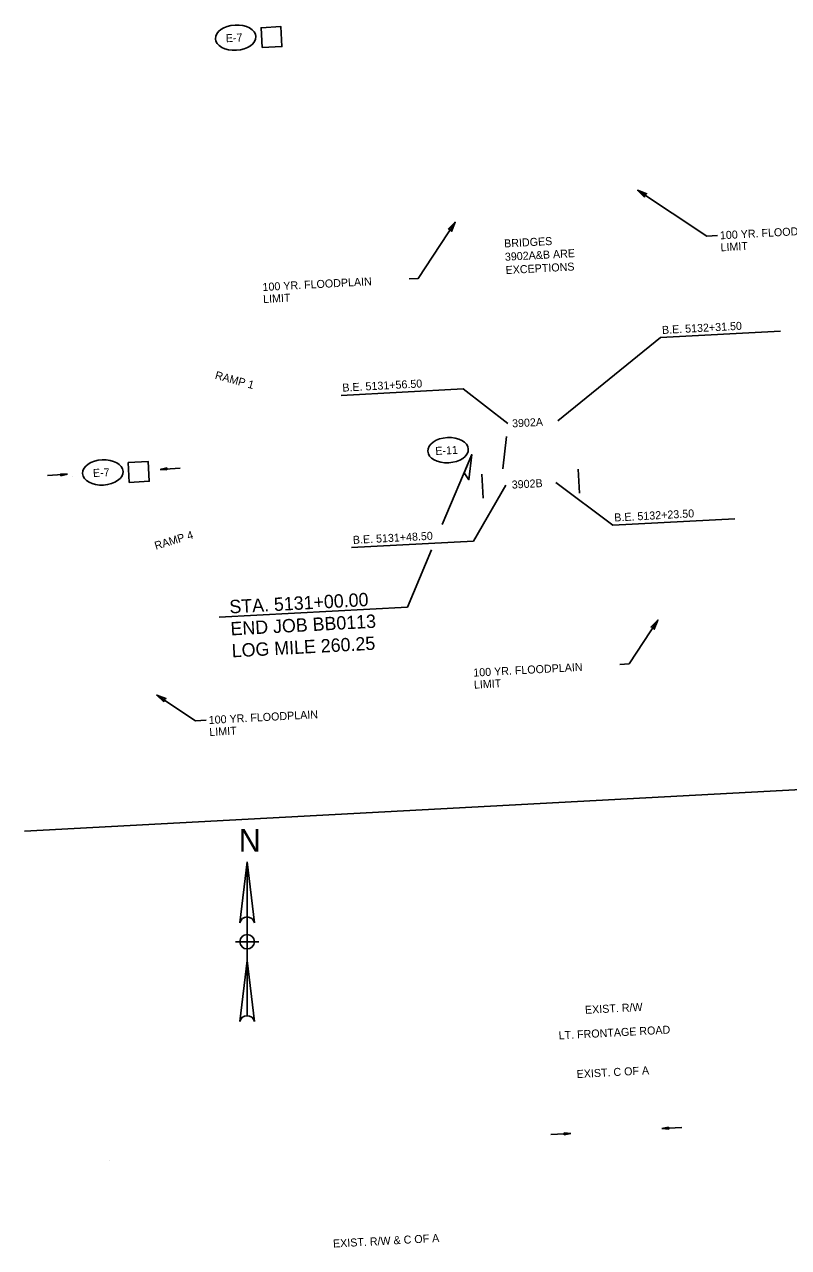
# Model space of a CAD drawing. Extents: x 257063 to 260260, y 223752 to 225802.
# Drawn here: x 257063 to 258210, y 223968 to 225802 of the extents above; entities that cross this region are included whole.
import ezdxf

# ---------------------------------------------------------------- set-up
doc = ezdxf.new("R2010")
doc.units = 0
for name, color, linetype in [('24X36', 7, 'Continuous'), ('DRAINAGE ARROWS', 7, 'Continuous'), ('Level 1', 7, 'Continuous'), ('Level 24', 7, 'Continuous'), ('Level 30', 7, 'Continuous'), ('Level 42', 7, 'Continuous'), ('Level 58', 7, 'Continuous'), ('Level 59', 7, 'Continuous'), ('R_Water Annot', 7, 'Continuous')]:
    doc.layers.add(name, color=color, linetype=linetype)

msp = doc.modelspace()

# ---------------------------------------------------------------- linework, layer by layer
at = {"layer": '24X36'}
msp.add_line((257786.5, 225183.7), (257781.1, 225135.4), dxfattribs=at)
for points in [[(257419.9, 225766.9), (257449.7, 225768.5), (257448.1, 225798.3), (257418.3, 225796.7)], [(257220.5, 225115), (257250.4, 225116.6), (257248.8, 225146.4), (257218.9, 225144.8)]]:
    msp.add_lwpolyline(points, close=True, dxfattribs=at)
at = {"layer": 'DRAINAGE ARROWS'}
for p, q in [((257117.9, 225128), (257127.9, 225127.1)), ((257118, 225125), (257117.9, 225128)), ((257117.9, 225127.8), (257126.3, 225127)), ((257117.9, 225127.5), (257124.5, 225126.9)), ((257117.9, 225127.3), (257122.9, 225126.8)), ((257117.9, 225127), (257121.2, 225126.7)), ((257117.9, 225126.8), (257119.5, 225126.6)), ((257118, 225125), (257127.9, 225127.1)), ((257118, 225125.3), (257126.3, 225127)), ((257118, 225125.5), (257124.5, 225126.9)), ((257118, 225125.8), (257122.9, 225126.8)), ((257118, 225126.1), (257121.2, 225126.7)), ((257118, 225126.3), (257119.5, 225126.6)), ((257276.8, 225136.6), (257266.9, 225134.5)), ((257276.9, 225133.6), (257266.9, 225134.5)), ((257276.8, 225136.3), (257268.5, 225134.6)), ((257276.9, 225133.8), (257268.5, 225134.6)), ((257276.8, 225136.1), (257270.3, 225134.7)), ((257276.9, 225134.1), (257270.3, 225134.7)), ((257276.8, 225135.8), (257271.9, 225134.8)), ((257276.9, 225134.3), (257271.9, 225134.8)), ((257276.8, 225135.6), (257273.6, 225134.9)), ((257276.9, 225134.6), (257273.6, 225134.9)), ((257276.9, 225135.3), (257275.3, 225135)), ((257276.9, 225134.8), (257275.3, 225135)), ((257276.9, 225133.6), (257276.8, 225136.6)), ((257873, 224139.8), (257883, 224138.8)), ((257873.1, 224136.8), (257873, 224139.8)), ((257873, 224139.5), (257881.4, 224138.7)), ((257873, 224139.3), (257879.7, 224138.6)), ((257873, 224139), (257878, 224138.5)), ((257873, 224138.8), (257876.3, 224138.5)), ((257873, 224138.5), (257874.6, 224138.4)), ((257873.1, 224136.8), (257883, 224138.8)), ((257873.1, 224137), (257881.4, 224138.7)), ((257873.1, 224137.3), (257879.7, 224138.6)), ((257873.1, 224137.8), (257876.3, 224138.5)), ((257873.1, 224137.5), (257878, 224138.5)), ((257873.1, 224138.1), (257874.6, 224138.4)), ((258029.8, 224148.2), (258019.9, 224146.2)), ((258030, 224145.2), (258019.9, 224146.2)), ((258029.8, 224148), (258021.6, 224146.2)), ((258030, 224145.5), (258021.6, 224146.2)), ((258029.8, 224147.7), (258023.3, 224146.3)), ((258029.9, 224145.7), (258023.3, 224146.3)), ((258029.8, 224147.5), (258024.9, 224146.4)), ((258029.9, 224146), (258024.9, 224146.4)), ((258029.9, 224147.2), (258026.6, 224146.5)), ((258029.9, 224146.2), (258026.6, 224146.5)), ((258029.9, 224146.9), (258028.3, 224146.6)), ((258029.9, 224146.5), (258028.3, 224146.6)), ((258030, 224145.2), (258029.8, 224148.2))]:
    msp.add_line(p, q, dxfattribs=at)
at = {"layer": 'Level 1'}
for p, q in [((257135.4, 225124.2), (257135.4, 225124.2)), ((257063.2, 224592.3), (258229, 224654.7)), ((257386.5, 224454.7), (257397.4, 224546.1)), ((257397.4, 224546.1), (257408.3, 224454.7)), ((257397.4, 224546.1), (257397.4, 224463.3)), ((257397.4, 224454.7), (257397.4, 224463.3)), ((257397.4, 224454.7), (257397.4, 224437.2)), ((257386.1, 224426.3), (257380, 224426.3)), ((257397.4, 224426.3), (257386.9, 224426.3)), ((257397.4, 224437.2), (257397.4, 224426.3)), ((257397.4, 224426.3), (257397.4, 224415.5)), ((257397.4, 224426.3), (257408.3, 224426.3)), ((257397.4, 224415.5), (257397.4, 224426.3)), ((257408.3, 224426.3), (257414.8, 224426.3)), ((257408.3, 224426.3), (257408.3, 224426.3)), ((257397.4, 224415.5), (257397.4, 224398)), ((257397.4, 224398), (257386.5, 224306.6)), ((257397.4, 224315.3), (257397.4, 224398)), ((257397.4, 224398), (257408.3, 224306.6)), ((257190.4, 224098.4), (257190.4, 224098.4))]:
    msp.add_line(p, q, dxfattribs=at)
for centre, radius, start, end in [((257397.4, 224452.2), 11.2, 90, 167.3196), ((257397.4, 224452.2), 11.2, 12.6804, 90), ((257397.4, 224426.3), 10.9, 90, 180), ((257397.4, 224426.3), 10.9, 180, 270), ((257397.4, 224426.3), 10.9, 0, 90), ((257397.4, 224426.3), 10.9, 270, 0), ((257397.4, 224304.2), 11.2, 90, 167.3196), ((257397.4, 224304.2), 11.2, 12.6804, 90)]:
    msp.add_arc(centre, radius, start, end, dxfattribs=at)
at = {"layer": 'Level 24'}
for p, q in [((258017.9, 225332), (257863.5, 225207.3)), ((258017.9, 225332), (258198, 225341.6)), ((257538.3, 225245.5), (257721.4, 225255.3)), ((257721.4, 225255.3), (257788.6, 225203.3)), ((257737.1, 225027), (257785.5, 225111)), ((257946.3, 225050.8), (257860.4, 225115)), ((257946.3, 225050.8), (258129.4, 225060.6)), ((257554, 225017.2), (257737.1, 225027))]:
    msp.add_line(p, q, dxfattribs=at)
for points in [[(258103.2, 225485.2), (258087.2, 225484.3), (257983.4, 225553.1)], [(257640.6, 225420.2), (257654.2, 225420.9), (257709.7, 225505.1)], [(257690.2, 225051.9), (257734.5, 225156.6)], [(257637.8, 224928), (257674.2, 225014)], [(257355.2, 224912.9), (257637.8, 224928)], [(257956.9, 224842), (257970.5, 224842.8), (258013.8, 224908.5)], [(257336.1, 224758.5), (257320.1, 224757.6), (257261.8, 224796.2)]]:
    msp.add_lwpolyline(points, dxfattribs=at)
at = {"layer": 'Level 30'}
for centre in [(257380.2, 225781.8), (257698.9, 225163.3), (257180.9, 225129.9)]:
    msp.add_ellipse(centre, major_axis=(30.4, 1.6), ratio=0.622507, dxfattribs=at)
at = {"layer": 'Level 42'}
for points in [[(257749.6, 225127.1), (257751.6, 225091.1)], [(257894.4, 225134.8), (257896.3, 225098.9)]]:
    msp.add_lwpolyline(points, dxfattribs=at)
at = {"layer": 'Level 58'}
for points in [[(257993.7, 225542.7), (257983.4, 225553.1), (257997, 225547.7), (257993.4, 225546.5)], [(257699.3, 225494.7), (257709.7, 225505.1), (257704.3, 225491.4), (257703.1, 225495.1)], [(258003.4, 224898.1), (258013.8, 224908.5), (258008.4, 224894.8), (258007.2, 224898.4)], [(257272.2, 224785.8), (257261.8, 224796.2), (257275.5, 224790.8), (257271.8, 224789.6)]]:
    msp.add_lwpolyline(points, close=True, dxfattribs=at)
at = {"layer": 'Level 59'}
msp.add_lwpolyline([(257723.1, 225129.5), (257734.5, 225156.6), (257730.2, 225119)], close=True, dxfattribs=at)
at = {"layer": 'R_Water Annot'}
for p, q in [((257098, 225125.5), (257127.9, 225127.1)), ((257117.9, 225128), (257127.9, 225127.1)), ((257118, 225125), (257117.9, 225128)), ((257117.9, 225127.8), (257126.3, 225127)), ((257117.9, 225127.5), (257124.5, 225126.9)), ((257117.9, 225127.3), (257122.9, 225126.8)), ((257117.9, 225127), (257121.2, 225126.7)), ((257117.9, 225126.8), (257119.5, 225126.6)), ((257118, 225125), (257127.9, 225127.1)), ((257118, 225125.3), (257126.3, 225127)), ((257118, 225125.5), (257124.5, 225126.9)), ((257118, 225125.8), (257122.9, 225126.8)), ((257118, 225126.1), (257121.2, 225126.7)), ((257118, 225126.3), (257119.5, 225126.6)), ((257276.8, 225136.6), (257266.9, 225134.5)), ((257296.8, 225136.2), (257266.9, 225134.5)), ((257276.9, 225133.6), (257266.9, 225134.5)), ((257276.8, 225136.3), (257268.5, 225134.6)), ((257276.9, 225133.8), (257268.5, 225134.6)), ((257276.8, 225136.1), (257270.3, 225134.7)), ((257276.9, 225134.1), (257270.3, 225134.7)), ((257276.8, 225135.8), (257271.9, 225134.8)), ((257276.9, 225134.3), (257271.9, 225134.8)), ((257276.8, 225135.6), (257273.6, 225134.9)), ((257276.9, 225134.6), (257273.6, 225134.9)), ((257276.9, 225135.3), (257275.3, 225135)), ((257276.9, 225134.8), (257275.3, 225135)), ((257276.9, 225133.6), (257276.8, 225136.6)), ((257853.1, 224137.3), (257883, 224138.8)), ((257873, 224139.8), (257883, 224138.8)), ((257873.1, 224136.8), (257873, 224139.8)), ((257873, 224139.5), (257881.4, 224138.7)), ((257873, 224139.3), (257879.7, 224138.6)), ((257873, 224139), (257878, 224138.5)), ((257873, 224138.8), (257876.3, 224138.5)), ((257873, 224138.5), (257874.6, 224138.4)), ((257873.1, 224136.8), (257883, 224138.8)), ((257873.1, 224137), (257881.4, 224138.7)), ((257873.1, 224137.3), (257879.7, 224138.6)), ((257873.1, 224137.8), (257876.3, 224138.5)), ((257873.1, 224137.5), (257878, 224138.5)), ((257873.1, 224138.1), (257874.6, 224138.4)), ((258029.8, 224148.2), (258019.9, 224146.2)), ((258049.9, 224147.8), (258019.9, 224146.2)), ((258030, 224145.2), (258019.9, 224146.2)), ((258029.8, 224148), (258021.6, 224146.2)), ((258030, 224145.5), (258021.6, 224146.2)), ((258029.8, 224147.7), (258023.3, 224146.3)), ((258029.9, 224145.7), (258023.3, 224146.3)), ((258029.8, 224147.5), (258024.9, 224146.4)), ((258029.9, 224146), (258024.9, 224146.4)), ((258029.9, 224147.2), (258026.6, 224146.5)), ((258029.9, 224146.2), (258026.6, 224146.5)), ((258029.9, 224146.9), (258028.3, 224146.6)), ((258029.9, 224146.5), (258028.3, 224146.6)), ((258030, 224145.2), (258029.8, 224148.2))]:
    msp.add_line(p, q, dxfattribs=at)

# ---------------------------------------------------------------- texts
at = {"layer": 'Level 1'}
msp.add_text('N', height=34.2, dxfattribs=at).set_placement((257384.8, 224561.2))
at = {"layer": 'Level 24'}
for s, height, rotation, p in [('100 YR. FLOODPLAIN', 12, 3.0666, (258107.2, 225479.4)), ('BRIDGES', 12, 3.0666, (257783.4, 225467.2)), ('LIMIT', 12, 3.0666, (258108.1, 225461.4)), ('3902A&B ARE', 12, 3.0666, (257784.5, 225447.2)), ('EXCEPTIONS', 12, 3.0666, (257785.6, 225427.3)), ('100 YR. FLOODPLAIN', 12, 3.0666, (257420.8, 225401.9)), ('LIMIT', 12, 3.0666, (257421.7, 225383.9)), ('B.E. 5132+31.50', 12, 3.0666, (258020.3, 225337.5)), ('RAMP 1', 12, 344.6899, (257348.3, 225270.6)), ('B.E. 5131+56.50', 12, 3.0666, (257540.6, 225251)), ('3902A', 12, 3.0666, (257795.3, 225197.4)), ('3902B', 12, 3.0666, (257794.8, 225105.6)), ('B.E. 5132+23.50', 12, 3.0666, (257948.6, 225056.3)), ('RAMP 4', 12, 16.9315, (257260.5, 225013.9)), ('B.E. 5131+48.50', 12, 3.0666, (257556.4, 225022.7)), ('STA. 5131+00.00', 20, 3.0667, (257371.3, 224918.5)), ('END JOB BB0113', 20, 3.0667, (257373, 224885.5)), ('LOG MILE 260.25', 20, 3.0667, (257374.8, 224852.6)), ('100 YR. FLOODPLAIN', 12, 3.0666, (257737.1, 224823.7)), ('LIMIT', 12, 3.0666, (257738, 224805.7)), ('100 YR. FLOODPLAIN', 12, 3.0666, (257340.1, 224752.7)), ('LIMIT', 12, 3.0666, (257341, 224734.7)), ('EXIST. R/W', 12, 3.0666, (257904.7, 224318.1)), ('LT. FRONTAGE ROAD', 12, 3.0666, (257865.2, 224279.7)), ('EXIST. C OF A', 12, 3.0666, (257892.2, 224221.8)), ('EXIST. R/W & C OF A', 12, 3.0666, (257526.6, 223967.7))]:
    msp.add_text(s, height=height, rotation=rotation, dxfattribs=at).set_placement(p)
at = {"layer": 'Level 30'}
for s, p in [('E-7', (257365.7, 225774.9)), ('E-11', (257680.1, 225156.1)), ('E-7', (257166.3, 225123))]:
    msp.add_text(s, height=12, rotation=3.0666, dxfattribs=at).set_placement(p)

doc.saveas('drawing.dxf')
